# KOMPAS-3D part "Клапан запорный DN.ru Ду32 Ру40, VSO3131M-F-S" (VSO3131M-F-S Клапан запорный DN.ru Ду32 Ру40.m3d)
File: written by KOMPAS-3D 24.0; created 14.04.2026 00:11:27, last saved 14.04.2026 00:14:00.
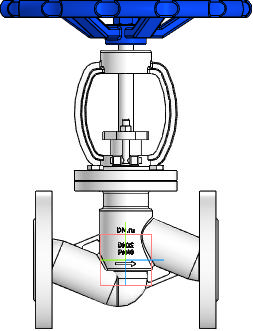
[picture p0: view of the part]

Document properties: Автор: R2D2; Полное имя файла: VSO3131M-F-S Клапан запорный DN.ru Ду32 Ру40.cdw

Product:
- Part/product: Клапан запорный DN.ru Ду32 Ру40  | designation VSO3131M-F-S
    Масса: 7.04
    Раздел спецификации: Прочие изделия
    Форматы листов документа: A2
    Примечание: D090-02140

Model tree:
1. Операция без истории:2

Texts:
  VSO3131M-F-S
